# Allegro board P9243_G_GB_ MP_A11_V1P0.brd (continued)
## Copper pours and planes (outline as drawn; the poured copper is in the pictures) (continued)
VBRIDGE on TOP: 41.92,20.77 41.92,20.79 39.9,22.81 39.88,22.81 39.88,27.98 39.01,28.85 39.01,30.62 39,30.63 39,43.85 39.88,44.73 39.88,44.74 40.94,45.8 42.52,45.8 42.56,45.84 42.59,45.84 42.63,45.8 46.05,45.8 46.63,45.21 46.63,45.03 46.64,45.03 46.64,40.63 46.98,40.3 47.7,40.3 48.41,39.58 48.41,38.93 48.29,38.8 46.3,38.8 46.29,38.81 44.47,38.82 44.07,38.82 43.83,38.59 43.83,29.68 45.14,28.37 45.68,28.37 46.63,27.42 46.63,26.4 46.89,26.14 46.89,23.29 46.87,23.27 46.87,22.35 47.3,21.92 47.54,21.92 47.72,21.73 47.72,20.85 47.64,20.77
N16670694 on TOP: 52.08,28.07 52.08,49.37 52.07,49.37 52.07,50.99 52.62,51.54 61.1,51.54 61.24,51.4 61.25,51.4 62.25,50.4 62.25,47.77 62.22,47.74 62.22,43.56 62.23,43.56 62.23,28.98 61.35,28.11 61.35,28.07
N16680668 on TOP: 38.65,23.08 38.82,23.08 38.99,22.91 38.99,21.8 39.12,21.66 39.53,21.66 39.58,21.71 39.58,23.16 39.17,23.57 38.52,23.57 38.38,23.43 38.38,23.24 38.53,23.08 38.65,23.08
N16680668 on TOP: 44.02,16.48 44.96,16.48 45.25,16.18 45.25,14.05 45.13,13.94 44.71,13.94 44.58,14.07 44.58,14.79 44.22,15.15 43.22,15.15 43.11,15.26 43.11,15.81 43.18,15.88 43.8,15.88 43.96,16.04 43.96,16.4 44.02,16.46
N16723656 on TOP: 48.29,27.36 48.29,26.22 47.97,25.9 47.97,24.99 47.27,24.99 47.13,25.14 47.13,26.18 47,26.31 46.91,26.31 46.75,26.47 46.75,27.23 46.92,27.4 48.22,27.4 48.28,27.35
N16723656 on TOP: 38.89,20.78 38.87,20.8 38.87,21.39 38.89,21.4 40.41,21.4 40.41,21.4 40.46,21.4 40.63,21.58 40.65,21.58 40.97,21.26 40.97,21.15 40.61,20.78
N16818106 on TOP: 37.61,27.6 37.61,26.9 37.71,26.8 38.27,26.8 38.33,26.87 38.33,27.48 38.73,27.87 38.73,28.03 38.33,28.42 38.19,28.42 37.6,27.83 37.6,27.6
N16818106 on TOP: 46.77,45.6 46.77,45.11 46.87,45.01 46.87,43.12 47.84,43.12 47.84,44.62 47.46,45.01 47.46,45.59 47.36,45.69 46.87,45.69 46.78,45.6
N16818106 on L2: 38.47,28.59 38.98,28.08 38.34,27.44 37.86,27.44 37.85,27.43 37.71,27.57 37.71,27.83
N17141402 on TOP: 44.07,30.43 44.03,30.47 44.03,30.75 44.03,30.75 43.92,30.86 43.92,31.14 44.11,31.32 44.11,33.08 44.83,33.08 44.84,33.07 44.84,30.88 44.84,30.87 44.84,30.65 44.62,30.43
N17141402 on TOP: 38.02,24.2 38.02,24.94 38.21,25.13 39.14,25.13 39.3,24.97 39.3,24.54 38.75,23.99 38.23,23.99
N17250859 on TOP: 5.56,38.63 5.19,39.01 5.19,42.82 5.41,43.05 7,43.05 7.23,42.81 7.23,42.32 7.3,42.25 8.38,42.25 8.38,42.21 8.39,42.21 8.39,41.9 8.38,41.91 7.2,41.91 6.88,41.59 6.88,39.93 7.15,39.67 8.38,39.67 8.38,39.36 7.32,39.36 7.24,39.27 7.24,38.8 7.07,38.63
N17250859 on BOTTOM: 13.21,51.05 15.49,51.05 15.75,50.8 15.75,48.77 15.49,48.51 13.21,48.51 12.95,48.77 12.95,50.8
N17250859 on L2: 4.83,40.13 4.57,40.39 4.57,44.2 5.33,44.96 9.65,44.96 10.41,45.72 10.41,51.05 10.92,51.56 16,51.56 16.51,51.05 16.51,41.15 15.49,40.13
N17356356 on TOP: 10.39,19.49 9.53,19.49 9.46,19.49 9.44,19.51 7.99,19.51 7.99,19.5 7.13,19.5 7.13,19.5 6.88,19.5 6.72,19.66 5.67,19.66 5.51,19.82 5.51,20.77 5.65,20.91 6.94,20.91 7.86,21.84 7.87,21.84 7.95,21.91 7.95,23.33 8.15,23.54 8.16,23.53 9.1,24.47 9.1,29.48 9.09,29.47 9.08,29.47 10.52,30.91 10.52,30.91 11.01,31.4 11.02,31.4 11.08,31.46 13.37,33.75 14.88,33.75 15.43,33.19 15.43,30.37 16.89,28.91 16.89,23.95 16.6,23.65 15.32,23.65 15.31,23.64 15.3,23.65 14.02,23.65 14.02,23.65 11,23.65 11,19.62 10.89,19.51 10.41,19.51
N17356356 on BOTTOM: 9.14,25.15 13.72,25.15 14.22,25.65 14.22,29.97 13.21,30.99 10.67,30.99 9.14,29.46
N17356362 on TOP: 11.41,23.35 15.37,23.35 15.37,23.35 16.67,23.35 17.08,22.95 17.08,20.15 16.42,19.49 15.28,19.49 15.28,19.48 11.33,19.48 11.22,19.59 11.22,23.17 11.41,23.35
N17356362 on BOTTOM: 14.73,19.56 14.48,19.81 14.48,30.23 13.21,31.5 13.21,47.75 13.72,48.26 16.26,48.26 16.51,48.01 16.51,44.96 17.53,43.94 17.53,31.5 18.03,30.99 18.03,20.07 17.53,19.56
N17401780 on TOP: 8.25,51.88 8.25,52.68 8.24,52.68 8.24,53.74 8.23,53.74 8.23,54.39 8.36,54.52 9.59,54.52 9.92,54.19 9.92,54.18 9.98,54.12 9.98,52.24 9.63,51.88
N17401780 on BOTTOM: 13.46,51.31 12.95,51.82 12.95,53.85 12.45,54.36 10.41,54.36 10.16,54.1 10.16,52.07 9.91,51.82 8.38,51.82 7.11,53.09 7.11,56.39 7.62,56.9 15.24,56.9 15.75,56.39 15.75,51.56 15.49,51.31

Small or netless copper shapes (teardrops, artwork), in the pictures only: 1 on TOP, 1 on L2

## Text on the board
Ref Des/Assembly Bottom: BOTTOM ASSEMBLY
Package Geometry/Pastemask Bottom: BOTTOM PASTE
Ref Des/Silkscreen Top: SCL | Y1 | SDA | GND | VIN | P9243_G_GB_MP_A11 V1P0 | November 2019
DIMENSION: GND2#7
User.8: GND1#2
User.15: BOARD OUTLINE
User.17: 11) BOW AND TWIST: SHOULD NOT EXCEED 0.007" PER INCH. | 12) PLATED PADS ON TOP AND BOTTOM MUST BE SAME HEIGHT AS CONDUCTOR PAD AND TRACE | 13) PLATING: IMMERSION GOLD FINISH. | 14) NO VENDOR LOGO OR NAME ON THE BOARD. | 16) CLIP SILKSCREEEN ON NO MASK AREA. | 10) DEBURR ALL SHARP EDGES | 15) BOARD MUST BE ROHS COMPLAINT. | 6) HOLE SIZE ARE FINISHED SIZE. | 3) BOARD THICKNESS : 0.062" +/-0.006". | 8) FOR LAYER BUILD UP SEE STACK UP DETAIL. | 1) FABRICATE BOARD PER IPC-A-600G | 2) MATERIAL FR4  4 LAYER BOARD. | 5) ALL HOLES ARE PLATED THROUGH UNLESS OTHERWISE SPECIFIED. | 7) SOLDER MASK BOTH SIDE WITH GREEN LIQUID PHOTO IMAGABLE. | 9) SILKSCREEN TOP SIDE "WHITE EPOXY" OVER SOLDER MASK | NOTES : | 4) MINIMUM PLATING IN ALL THE THROUGH HOLE SHALL BE 0.001 INCH Cu.
User.19: BOARD DIMENSIONS ARE IN INCH[MM] | STACK UP DETAILS: | BOTTOM -   1OZ | TOP  -    1OZ | L1   -    1OZ | L2    -   1OZ
User.20: BOTTOM SILK
User.26: FIGURE | FINISHED_SIZE | 10.0 | 12.0 | 20.0 | 30.0 | 40.0 | 125.98 | 157.48 | 135.0 | 33.461x25.591 | 46.0x24.0 | 59.059x32.48 | 38.0x30.0 | 250.0x8.0 | 320.0x8.0 | ROTATION | - | 0.000 | 90.000 | DRILL CHART: TOP to BOTTOM | ALL UNITS ARE IN MILS | TOLERANCE_DRILL | +3.0/-3.0 | +4.0/-4.0 | +2.0/-2.0 | TOLERANCE_TRAVEL | +0.0/-0.0 | PLATED | NON-PLATED | QTY | 2 | 270 | 6 | 24 | 72 | 38 | 9 | 3 | 1 | 4
